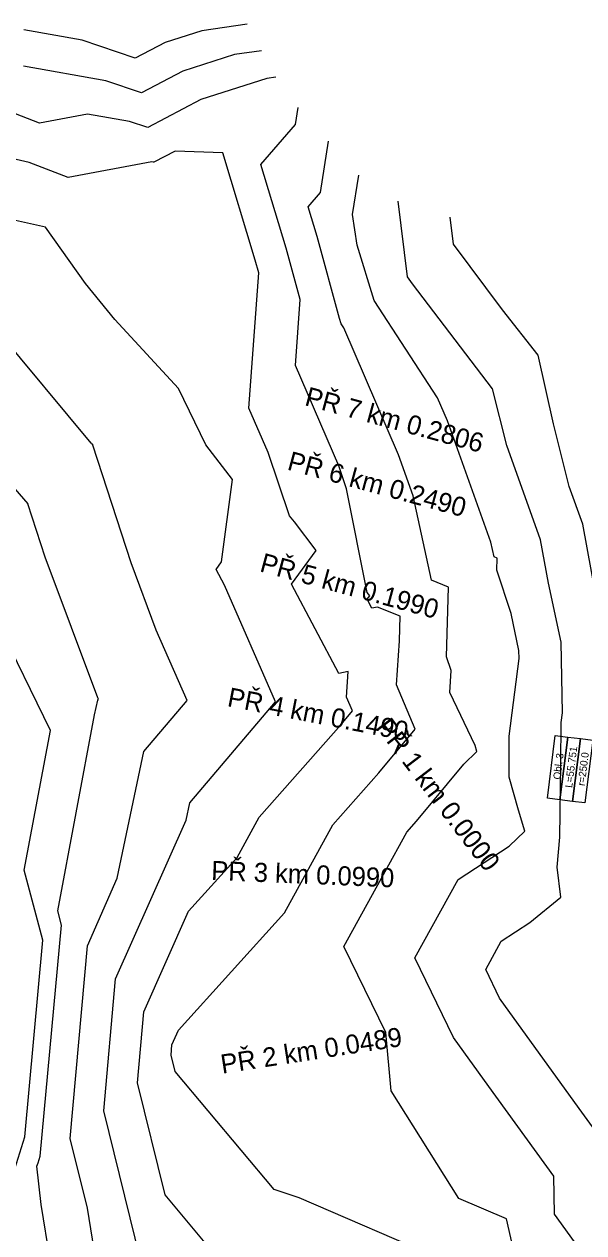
# Model space of a CAD drawing. Extents: x -549394 to -546608, y -1037055 to -1033629.
# Drawn here: x -548203 to -547937, y -1034671 to -1034097 of the extents above; entities that cross this region are included whole.
import ezdxf

# ---------------------------------------------------------------- set-up
doc = ezdxf.new("R2010")
doc.units = 0
for name, color, linetype in [('hlavni_vrst', 7, 'Continuous'), ('norm_vrst', 7, 'Continuous'), ('x_popis_oblouky_C211', 7, 'Continuous'), ('x_popis_pricne_rezy_C211', 7, 'Continuous')]:
    doc.layers.add(name, color=color, linetype=linetype)

msp = doc.modelspace()

# ---------------------------------------------------------------- linework, layer by layer
at = {"layer": 'hlavni_vrst'}
for p, q in [((-548096.94, -1034097.48), (-548118.44, -1034100.6)), ((-548175.36, -1034105.02), (-548202.96, -1034100.19)), ((-548118.44, -1034100.6), (-548135.98, -1034106.21)), ((-548150.1, -1034113.64), (-548175.36, -1034105.02)), ((-548135.98, -1034106.21), (-548150.1, -1034113.64)), ((-548046.91, -1034187.76), (-548044.02, -1034169.05)), ((-548044.83, -1034202.37), (-548046.91, -1034187.76)), ((-548036.74, -1034228.59), (-548044.83, -1034202.37)), ((-548006.62, -1034274.76), (-548036.74, -1034228.59)), ((-548170.98, -1034296.28), (-548216.76, -1034241.3)), ((-548001.95, -1034285.63), (-548006.62, -1034274.76)), ((-547981.29, -1034343.22), (-548001.95, -1034285.63)), ((-548170.98, -1034296.28), (-548170.17, -1034297.21)), ((-548152.12, -1034353), (-548170.17, -1034297.21)), ((-547979.78, -1034350.17), (-547981.29, -1034343.22)), ((-548140.11, -1034384.99), (-548152.12, -1034353)), ((-547978.36, -1034350.74), (-547979.78, -1034350.17)), ((-547978.53, -1034356.48), (-547978.36, -1034350.74)), ((-547971.7, -1034377.02), (-547978.53, -1034356.48)), ((-547967.97, -1034394.56), (-547971.7, -1034377.02)), ((-548125.53, -1034418.32), (-548140.11, -1034384.99)), ((-547967.9, -1034398.42), (-547967.97, -1034394.56)), ((-547972.53, -1034435.18), (-547967.9, -1034398.42)), ((-548146.08, -1034442.45), (-548125.53, -1034418.32)), ((-547972.63, -1034454.59), (-547972.53, -1034435.18)), ((-548158.61, -1034502.63), (-548146.08, -1034442.45)), ((-547968.22, -1034470.29), (-547972.63, -1034454.59)), ((-547965.24, -1034480.24), (-547968.22, -1034470.29)), ((-547972.63, -1034487.41), (-547965.24, -1034480.24)), ((-547996.78, -1034503.15), (-547972.63, -1034487.41)), ((-548172.84, -1034534.63), (-548158.61, -1034502.63)), ((-548017.39, -1034540.43), (-547996.78, -1034503.15)), ((-548181.01, -1034626.04), (-548172.84, -1034534.63)), ((-547998.99, -1034578.18), (-548017.39, -1034540.43)), ((-547982.19, -1034601.45), (-547998.99, -1034578.18)), ((-547951.4, -1034643.89), (-547982.19, -1034601.45)), ((-548172.85, -1034659.09), (-548181.01, -1034626.04)), ((-547951.14, -1034661.91), (-547951.4, -1034643.89)), ((-548164.9, -1034707.86), (-548172.85, -1034659.09)), ((-547933.58, -1034685.98), (-547951.14, -1034661.91))]:
    msp.add_line(p, q, dxfattribs=at)
at = {"layer": 'norm_vrst'}
for p, q in [((-548103.06, -1034111.93), (-548127.48, -1034119.75)), ((-548090.16, -1034110.06), (-548103.06, -1034111.93)), ((-548164.09, -1034124.3), (-548203.12, -1034117.47)), ((-548127.48, -1034119.75), (-548147.14, -1034130.08)), ((-548147.14, -1034130.08), (-548164.09, -1034124.3)), ((-548087.68, -1034123.26), (-548118.97, -1034133.28)), ((-548083.38, -1034122.64), (-548087.68, -1034123.26)), ((-548195.52, -1034144.43), (-548228.86, -1034131.43)), ((-548118.97, -1034133.28), (-548144.17, -1034146.53)), ((-548074.05, -1034145.06), (-548072.8, -1034136.95)), ((-548172.71, -1034140.1), (-548195.52, -1034144.43)), ((-548152.81, -1034143.58), (-548172.71, -1034140.1)), ((-548144.17, -1034146.53), (-548152.81, -1034143.58)), ((-548090.47, -1034164.1), (-548074.05, -1034145.06)), ((-548062.16, -1034177.32), (-548058.41, -1034153)), ((-548200.54, -1034163.04), (-548228.12, -1034156.87)), ((-548131.11, -1034157.66), (-548141.21, -1034162.97)), ((-548108.58, -1034158.52), (-548131.11, -1034157.66)), ((-548093.11, -1034209.4), (-548108.58, -1034158.52)), ((-548182.01, -1034170.26), (-548200.54, -1034163.04)), ((-548142.31, -1034162.72), (-548182.01, -1034170.26)), ((-548141.54, -1034162.86), (-548142.31, -1034162.72)), ((-548141.21, -1034162.97), (-548141.54, -1034162.86)), ((-548078.41, -1034203.78), (-548090.47, -1034164.1)), ((-548067.98, -1034184.08), (-548062.16, -1034177.32)), ((-548020.94, -1034217.33), (-548025.31, -1034181.5)), ((-548192.71, -1034193.76), (-548220.67, -1034187.5)), ((-548063.71, -1034198.15), (-548067.98, -1034184.08)), ((-547999.06, -1034201.83), (-548000.62, -1034188.97)), ((-548173.66, -1034220.47), (-548192.71, -1034193.76)), ((-548053.08, -1034237.07), (-548063.71, -1034198.15)), ((-548071.79, -1034228.02), (-548078.41, -1034203.78)), ((-547975.76, -1034233.04), (-547999.06, -1034201.83)), ((-548091.47, -1034215.42), (-548093.11, -1034209.4)), ((-548096.11, -1034279.6), (-548091.47, -1034215.42)), ((-548018.45, -1034220.67), (-548020.94, -1034217.33)), ((-548159.81, -1034237.49), (-548173.66, -1034220.47)), ((-547980.47, -1034270.47), (-548018.45, -1034220.67)), ((-548074.06, -1034259.46), (-548071.79, -1034228.02)), ((-547958.91, -1034254.56), (-547975.76, -1034233.04)), ((-548129.59, -1034270.3), (-548159.81, -1034237.49)), ((-548052.28, -1034239.68), (-548053.08, -1034237.07)), ((-548051.12, -1034241.45), (-548052.28, -1034239.68)), ((-548025.21, -1034301.74), (-548051.12, -1034241.45)), ((-547951.58, -1034287.04), (-547958.91, -1034254.56)), ((-548053.48, -1034306.91), (-548074.06, -1034259.46)), ((-548116.62, -1034297.06), (-548129.59, -1034270.3)), ((-547973.74, -1034297.27), (-547980.47, -1034270.47)), ((-548086.96, -1034300.69), (-548096.11, -1034279.6)), ((-547944.13, -1034316.72), (-547951.58, -1034287.04)), ((-548229.05, -1034292.94), (-548201.05, -1034324.93)), ((-548103.98, -1034313.47), (-548116.62, -1034297.06)), ((-547957.72, -1034342.04), (-547973.74, -1034297.27)), ((-548076.87, -1034330.67), (-548086.96, -1034300.69)), ((-548018.23, -1034321.19), (-548025.21, -1034301.74)), ((-548049.76, -1034317.95), (-548053.48, -1034306.91)), ((-548109.2, -1034352.59), (-548103.98, -1034313.47)), ((-548040.02, -1034367.09), (-548049.76, -1034317.95)), ((-548009.54, -1034361.22), (-548018.23, -1034321.19)), ((-547937.7, -1034334.69), (-547944.13, -1034316.72)), ((-548192.87, -1034350.24), (-548201.05, -1034324.93)), ((-548074.48, -1034333.52), (-548076.87, -1034330.67)), ((-548064.23, -1034347.16), (-548074.48, -1034333.52)), ((-547929.16, -1034381.23), (-547937.7, -1034334.69)), ((-547953.95, -1034362.58), (-547957.72, -1034342.04)), ((-548075.87, -1034363.19), (-548064.23, -1034347.16)), ((-548167.8, -1034417), (-548192.87, -1034350.24)), ((-548111.76, -1034356.12), (-548109.2, -1034352.59)), ((-548190.3, -1034432.56), (-548227.23, -1034357.2)), ((-548107.75, -1034363.65), (-548111.76, -1034356.12)), ((-548001.39, -1034364.5), (-548009.54, -1034361.22)), ((-548083.54, -1034418.98), (-548107.75, -1034363.65)), ((-548053.41, -1034405.42), (-548075.87, -1034363.19)), ((-548038.82, -1034368.68), (-548040.02, -1034367.09)), ((-548002.31, -1034397.6), (-548001.39, -1034364.5)), ((-547947.99, -1034390.61), (-547953.95, -1034362.58)), ((-548039.98, -1034370.27), (-548038.82, -1034368.68)), ((-548037.75, -1034374.46), (-548039.98, -1034370.27)), ((-548035.1, -1034373.96), (-548037.75, -1034374.46)), ((-548024.41, -1034378.26), (-548035.1, -1034373.96)), ((-548024.74, -1034389.95), (-548024.41, -1034378.26)), ((-548026.05, -1034410.86), (-548024.74, -1034389.95)), ((-547947.33, -1034424.17), (-547947.99, -1034390.61)), ((-548000.17, -1034404.06), (-548002.31, -1034397.6)), ((-548049.01, -1034404.59), (-548053.41, -1034405.42)), ((-548049.77, -1034416.71), (-548049.01, -1034404.59)), ((-548000.83, -1034414.53), (-548000.17, -1034404.06)), ((-548017.25, -1034431.88), (-548026.05, -1034410.86)), ((-548169.38, -1034425.17), (-548167.91, -1034418.13)), ((-548167.91, -1034418.13), (-548167.51, -1034417.65)), ((-548167.51, -1034417.65), (-548167.8, -1034417)), ((-548047.04, -1034423.24), (-548049.77, -1034416.71)), ((-547988.82, -1034439.7), (-548000.83, -1034414.53)), ((-548124.25, -1034466.77), (-548083.54, -1034418.98)), ((-548052.38, -1034429.67), (-548047.04, -1034423.24)), ((-547947.9, -1034428.68), (-547947.33, -1034424.17)), ((-548186.88, -1034518.02), (-548169.38, -1034425.17)), ((-548091.3, -1034473.64), (-548052.38, -1034429.67)), ((-547948, -1034448.39), (-547947.9, -1034428.68)), ((-548202.78, -1034498.76), (-548190.3, -1034432.56)), ((-548034.46, -1034452.59), (-548017.25, -1034431.88)), ((-547987.96, -1034442.56), (-547988.82, -1034439.7)), ((-547994.11, -1034448.52), (-547987.96, -1034442.56)), ((-548056.24, -1034477.2), (-548034.46, -1034452.59)), ((-548016.54, -1034475.52), (-547994.11, -1034448.52)), ((-547948.63, -1034483.2), (-547948, -1034448.39)), ((-548125.98, -1034475.07), (-548124.25, -1034466.77)), ((-548159.45, -1034550.3), (-548125.98, -1034475.07)), ((-548101.78, -1034492.75), (-548091.3, -1034473.64)), ((-548021.17, -1034480.75), (-548016.54, -1034475.52)), ((-548079.18, -1034519.05), (-548056.24, -1034477.2)), ((-548031.4, -1034499.41), (-548021.17, -1034480.75)), ((-547949.87, -1034497.33), (-547948.63, -1034483.2)), ((-548124.79, -1034518.16), (-548101.78, -1034492.75)), ((-548193.98, -1034532.04), (-548202.78, -1034498.76)), ((-547948.03, -1034511.62), (-547949.87, -1034497.33)), ((-548051.05, -1034534.94), (-548031.4, -1034499.41)), ((-547962.73, -1034523.65), (-547948.03, -1034511.62)), ((-548185.07, -1034524.89), (-548186.88, -1034518.02)), ((-548146.06, -1034565.97), (-548124.79, -1034518.16)), ((-548129.58, -1034574.7), (-548079.18, -1034519.05)), ((-548195.18, -1034634.51), (-548185.07, -1034524.89)), ((-547976.34, -1034532.53), (-547962.73, -1034523.65)), ((-548202.58, -1034625.32), (-548193.98, -1034532.04)), ((-547983.74, -1034545.91), (-547976.34, -1034532.53)), ((-548031.16, -1034575.74), (-548051.05, -1034534.94)), ((-548165.04, -1034612.88), (-548159.45, -1034550.3)), ((-547977.13, -1034559.46), (-547983.74, -1034545.91)), ((-547939.34, -1034611.82), (-547977.13, -1034559.46)), ((-548149.08, -1034599.71), (-548146.06, -1034565.97)), ((-548132.68, -1034581.65), (-548129.58, -1034574.7)), ((-548028.57, -1034603.4), (-548031.16, -1034575.74)), ((-548133.11, -1034586.55), (-548132.68, -1034581.65)), ((-548131.21, -1034594.26), (-548133.11, -1034586.55)), ((-548084.19, -1034650.32), (-548131.21, -1034594.26)), ((-548135.97, -1034652.77), (-548149.08, -1034599.71)), ((-547996.51, -1034654.45), (-548028.57, -1034603.4)), ((-548146.55, -1034687.75), (-548165.04, -1034612.88)), ((-547930.54, -1034623.95), (-547939.34, -1034611.82)), ((-548208.07, -1034642.95), (-548202.58, -1034625.32)), ((-548196.13, -1034637.57), (-548195.18, -1034634.51)), ((-548196.89, -1034639.11), (-548196.13, -1034637.57)), ((-548194.75, -1034657.36), (-548196.89, -1034639.11)), ((-548116.13, -1034676.43), (-548135.97, -1034652.77)), ((-548072.27, -1034654.17), (-548084.19, -1034650.32)), ((-548184.93, -1034717.6), (-548194.75, -1034657.36)), ((-547999.8, -1034685.36), (-548072.27, -1034654.17)), ((-547973.84, -1034664.21), (-547996.51, -1034654.45)), ((-547956.64, -1034741.01), (-547973.84, -1034664.21))]:
    msp.add_line(p, q, dxfattribs=at)
at = {"layer": 'x_popis_oblouky_C211'}
for points in [[(-547954.47, -1034464.64), (-547950.72, -1034434.87), (-547944.77, -1034435.62), (-547948.51, -1034465.39)], [(-547948.51, -1034465.39), (-547944.77, -1034435.62), (-547938.81, -1034436.37), (-547942.56, -1034466.14)], [(-547942.56, -1034466.14), (-547938.81, -1034436.37), (-547932.86, -1034437.12), (-547936.61, -1034466.89)]]:
    msp.add_lwpolyline(points, close=True, dxfattribs=at)

# ---------------------------------------------------------------- texts
for s, p in [('L=55.751', (-547942.72, -1034459.86)), ('Obl. 3', (-547948.28, -1034455.93)), ('r=250.0', (-547936.74, -1034458.97))]:
    msp.add_text(s, height=3.5, rotation=82.84387, dxfattribs=at).set_placement(p)
at = {"layer": 'x_popis_pricne_rezy_C211'}
for s, rotation, p in [('PŘ 7 km 0.2806', 344.86016, (-548070.13, -1034278.12)), ('PŘ 6 km 0.2490', 344.86016, (-548078.4, -1034308.68)), ('PŘ 5 km 0.1990', 344.86016, (-548091.46, -1034356.95)), ('PŘ 4 km 0.1490', 349.01271, (-548106.81, -1034420.92)), ('PŘ 1 km 0.0000', 307.30776, (-548036.17, -1034431.03)), ('PŘ 3 km 0.0990', 357.63656, (-548114.16, -1034503.39)), ('PŘ 2 km 0.0489', 8.73735, (-548108.82, -1034595.36))]:
    msp.add_text(s, height=9.0627, rotation=rotation, dxfattribs=at).set_placement(p)

doc.saveas('drawing.dxf')
